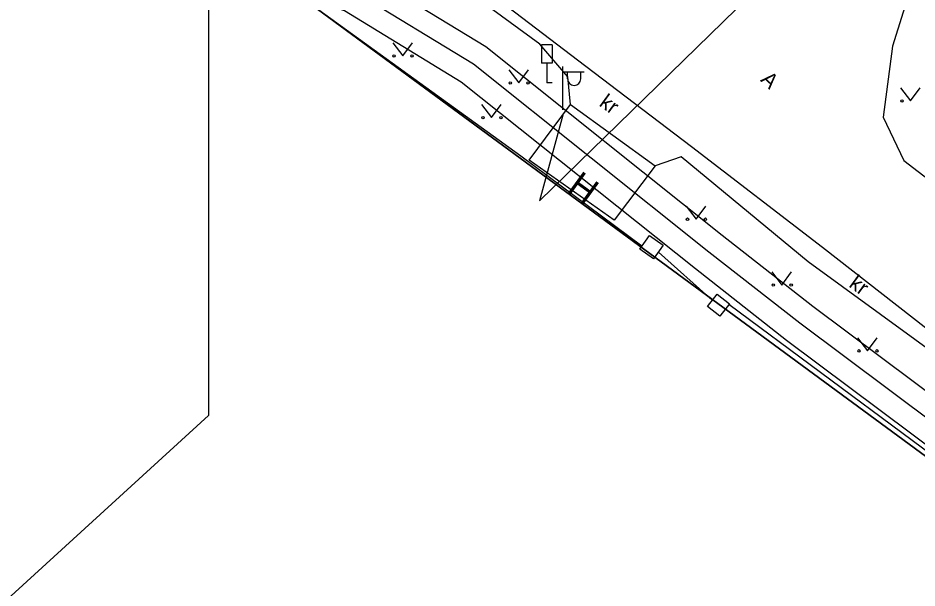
# Model space of a CAD drawing. Extents: x 554947 to 555436, y 6564938 to 6565792.
# Drawn here: x 555228.52 to 555270.11, y 6565557.19 to 6565583.53 of the extents above; entities that cross this region are included whole.
import ezdxf

# ---------------------------------------------------------------- set-up
doc = ezdxf.new("R2010")
doc.units = 0
for name, color, linetype in [('AED', 7, 'Continuous'), ('HALJASTUS', 7, 'Continuous'), ('HOONE', 7, 'Continuous'), ('KASUTUSALA', 7, 'Continuous'), ('LIIKLUS', 7, 'Continuous'), ('MPOHULIIN', 7, 'Continuous'), ('PIIR', 7, 'Continuous'), ('POST', 7, 'Continuous'), ('PR_SIDE', 7, 'Continuous'), ('TEE', 7, 'Continuous')]:
    doc.layers.add(name, color=color, linetype=linetype)

msp = doc.modelspace()

# ---------------------------------------------------------------- linework, layer by layer
at = {"layer": 'AED'}
msp.add_line((555258.145, 6565572.717), (555260.639, 6565570.489), dxfattribs=at)
for points in [[(555257.388, 6565572.989), (555251.782, 6565577.142), (555242.434, 6565583.901), (555242.233, 6565583.941), (555233.453, 6565584.321)], [(555301.646, 6565540.531), (555292.158, 6565547.42), (555274.134, 6565560.859), (555261.407, 6565570.297)]]:
    msp.add_lwpolyline(points, dxfattribs=at)
for points in [[(555257.729, 6565573.48), (555258.367, 6565573.036), (555257.924, 6565572.398), (555257.286, 6565572.842)], [(555260.862, 6565570.773), (555261.431, 6565570.327), (555260.985, 6565569.759), (555260.417, 6565570.205)]]:
    msp.add_lwpolyline(points, close=True, dxfattribs=at)
at = {"layer": 'HALJASTUS'}
for p, q in [((555245.859, 6565582.387), (555246.322, 6565581.78)), ((555246.322, 6565581.78), (555246.768, 6565582.387)), ((555251.23, 6565581.141), (555251.694, 6565580.534)), ((555251.694, 6565580.534), (555252.139, 6565581.141)), ((555269.351, 6565580.306), (555269.814, 6565579.699)), ((555269.814, 6565579.699), (555270.26, 6565580.306)), ((555249.97, 6565579.541), (555250.433, 6565578.934)), ((555250.433, 6565578.934), (555250.879, 6565579.541)), ((555259.431, 6565574.842), (555259.895, 6565574.235)), ((555259.895, 6565574.235), (555260.34, 6565574.842)), ((555263.398, 6565571.799), (555263.862, 6565571.192)), ((555263.862, 6565571.192), (555264.307, 6565571.799)), ((555267.366, 6565568.756), (555267.829, 6565568.149)), ((555267.829, 6565568.149), (555268.275, 6565568.756))]:
    msp.add_line(p, q, dxfattribs=at)
for centre in [(555245.921, 6565581.78), (555246.75, 6565581.78), (555251.293, 6565580.534), (555252.121, 6565580.534), (555269.413, 6565579.699), (555250.032, 6565578.934), (555250.861, 6565578.934), (555259.494, 6565574.235), (555260.322, 6565574.235), (555263.461, 6565571.192), (555264.29, 6565571.192), (555267.428, 6565568.149), (555268.257, 6565568.149)]:
    msp.add_circle(centre, 0.055, dxfattribs=at)
at = {"layer": 'HOONE'}
msp.add_lwpolyline([(555257.995, 6565576.697), (555256.108, 6565574.186), (555252.169, 6565576.961), (555254.087, 6565579.537), (555257.995, 6565576.697)], dxfattribs=at)
at = {"layer": 'KASUTUSALA'}
msp.add_lwpolyline([(555282.937, 6565554.541), (555264.078, 6565568.633), (555259.865, 6565571.933), (555249.017, 6565580.573), (555243.622, 6565583.862), (555238.34, 6565585.678), (555238.34, 6565584.092), (555236.34, 6565584.168), (555236.34, 6565586.946), (555231.217, 6565605.702), (555233.309, 6565605.634), (555234.35, 6565605.6), (555235.803, 6565604.987), (555234.66, 6565604.12), (555233.701, 6565604.199), (555238.103, 6565588.08), (555238.166, 6565587.854), (555238.34, 6565587.793), (555244.478, 6565585.683), (555250.166, 6565582.216), (555261.104, 6565573.503), (555265.293, 6565570.221), (555284.174, 6565556.114)], dxfattribs=at)
at = {"layer": 'LIIKLUS'}
for p, q in [((555252.739, 6565582.29), (555252.739, 6565581.44)), ((555253.239, 6565582.29), (555252.739, 6565582.29)), ((555253.239, 6565582.29), (555253.239, 6565581.44)), ((555253.239, 6565581.44), (555252.739, 6565581.44)), ((555252.989, 6565581.44), (555252.989, 6565580.54)), ((555253.239, 6565580.54), (555252.989, 6565580.54))]:
    msp.add_line(p, q, dxfattribs=at)
at = {"layer": 'MPOHULIIN'}
msp.add_line((555253.72, 6565579.044), (555252.652, 6565575.082), dxfattribs=at)
msp.add_lwpolyline([(555252.652, 6565575.082), (555268.428, 6565590.453)], dxfattribs=at)
at = {"layer": 'PIIR'}
msp.add_lwpolyline([(555393.069, 6565560.972), (555353.12, 6565523.87), (555343.14, 6565512.46), (555302.6, 6565539.71), (555242.37, 6565583.94), (555179.42, 6565586.32), (555138.98, 6565580.6), (555121.18, 6565602.26), (555116.17, 6565610.5), (555109.96, 6565624.83), (555093.56, 6565628.47), (555079.04, 6565618.4), (555074.13, 6565607.82), (555075.34, 6565593.24), (555091.74, 6565551.94), (555171.91, 6565394.64), (555191.35, 6565341.19), (555195.08, 6565294.61), (555195.28, 6565271.63), (555191.64, 6565237.48)], dxfattribs=at)
msp.add_lwpolyline([(555121.18, 6565602.26), (555138.98, 6565580.6), (555179.42, 6565586.32), (555242.37, 6565583.94), (555302.6, 6565539.71), (555287.77, 6565518.56), (555207.29, 6565506.14), (555200.64, 6565496.23), (555185.97, 6565502.75), (555177.68, 6565506.44), (555171.49, 6565510.85), (555162.05, 6565514.45), (555140.65, 6565513.25), (555139.49, 6565523.98), (555139.26, 6565529.51), (555141.68, 6565537.52), (555139.64, 6565543.1), (555131.01, 6565550.06), (555126.35, 6565558.74), (555119.63, 6565564.84), (555105.26, 6565587.71), (555099.5, 6565594.91), (555116.17, 6565610.5)], close=True, dxfattribs=at)
at = {"layer": 'POST'}
for p, q in [((555253.72, 6565579.294), (555253.72, 6565581.294)), ((555253.72, 6565581.044), (555254.72, 6565581.044)), ((555253.946, 6565580.723), (555253.946, 6565581.044)), ((555254.559, 6565580.723), (555254.559, 6565581.044)), ((555253.72, 6565579.044), (555253.72, 6565579.044))]:
    msp.add_line(p, q, dxfattribs=at)
msp.add_arc((555254.253, 6565580.723), 0.306, 180, 0, dxfattribs=at)
at = {"layer": 'PR_SIDE'}
for points in [[(555309.687, 6565535.684), (555303.916, 6565540.202), (555288.808, 6565550.982), (555283.555, 6565555.328), (555264.686, 6565569.427), (555260.485, 6565572.718), (555249.591, 6565581.395), (555244.05, 6565584.772), (555237.34, 6565587.08), (555232.399, 6565605.169), (555232.137, 6565606.132)], [(555237.34, 6565587.08), (555237.34, 6565565.16), (555226.585, 6565555.364), (555203.636, 6565543.731), (555203.636, 6565538.53), (555204.984, 6565533.828), (555204.645, 6565532.63)]]:
    msp.add_lwpolyline(points, dxfattribs=at)
at = {"layer": 'TEE'}
for points in [[(555309.906, 6565538.03), (555305.168, 6565541.808), (555305.066, 6565542.334), (555294.766, 6565550.531), (555276.823, 6565564.276), (555265.732, 6565572.927), (555259.684, 6565577.587), (555254.787, 6565581.289), (555247.931, 6565586.532), (555243.893, 6565589.125), (555239.934, 6565591.048), (555235.042, 6565592.642), (555234.652, 6565590.428), (555233.978, 6565588.723)], [(555254.087, 6565579.537), (555253.958, 6565580.81), (555252.655, 6565582.326), (555247.572, 6565586.061), (555243.345, 6565588.774), (555239.362, 6565590.351), (555234.652, 6565590.428)], [(555272.683, 6565590.134), (555271.484, 6565588.076), (555270.516, 6565586.416), (555269.723, 6565584.609), (555268.981, 6565582.24), (555268.55, 6565578.954), (555269.504, 6565576.952), (555281.044, 6565568.103), (555297.768, 6565555.508), (555316.66, 6565541.129), (555323.074, 6565536.252), (555328.036, 6565533.009), (555332.837, 6565530.879), (555337.611, 6565529.695), (555343.363, 6565529.946), (555348.456, 6565531.532), (555353.801, 6565534.677), (555358.561, 6565538.499)], [(555304.166, 6565537.744), (555304.47, 6565538.257), (555305.035, 6565540.465), (555305.168, 6565541.808), (555294.581, 6565550.293), (555276.533, 6565563.926), (555265.084, 6565572.259), (555259.201, 6565577.119), (555257.995, 6565576.697)]]:
    msp.add_lwpolyline(points, dxfattribs=at)

# ---------------------------------------------------------------- texts
at = {"layer": 'HOONE'}
msp.add_text('H', height=1.2, rotation=323.9607, dxfattribs=at).set_placement((555253.858, 6565575.537))
at = {"layer": 'TEE'}
for s, rotation, p in [('A', 316.1056, (555262.838, 6565580.641)), ('kr', 323.9607, (555255.366, 6565579.505)), ('kr', 323.9052, (555266.922, 6565571.139))]:
    msp.add_text(s, height=0.7, rotation=rotation, dxfattribs=at).set_placement(p)

doc.saveas('drawing.dxf')
